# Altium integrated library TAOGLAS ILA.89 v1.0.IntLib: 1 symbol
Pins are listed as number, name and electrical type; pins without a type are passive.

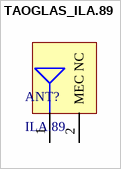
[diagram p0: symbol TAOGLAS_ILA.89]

## TAOGLAS_ILA.89
designator ANT?, comment ILA.89
LTCC ISM Chip Antenna Covering 868/915MHz; ComponentLibStatus: Created; MFG: Taoglas; Temp_High: +85C; Temp_Low: -40C
footprint TAOGLAS_ILA.89 (LTCC ISM Chip Antenna Covering 868/915MHz)
pins: 1 RF OUT, 2 MEC NC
